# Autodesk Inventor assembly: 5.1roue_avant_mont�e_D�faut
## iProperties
Created: 2011-01
Part Number: 5.1roue_avant_mont�e_D�faut
Document SubType Name: Assembly
Designer: eric
Mass: 293.57 g
Surface Area: 1571.94 cm^2
Volume: 293.57 cm^3
Density: 1 g/cm^3
Author: eric
